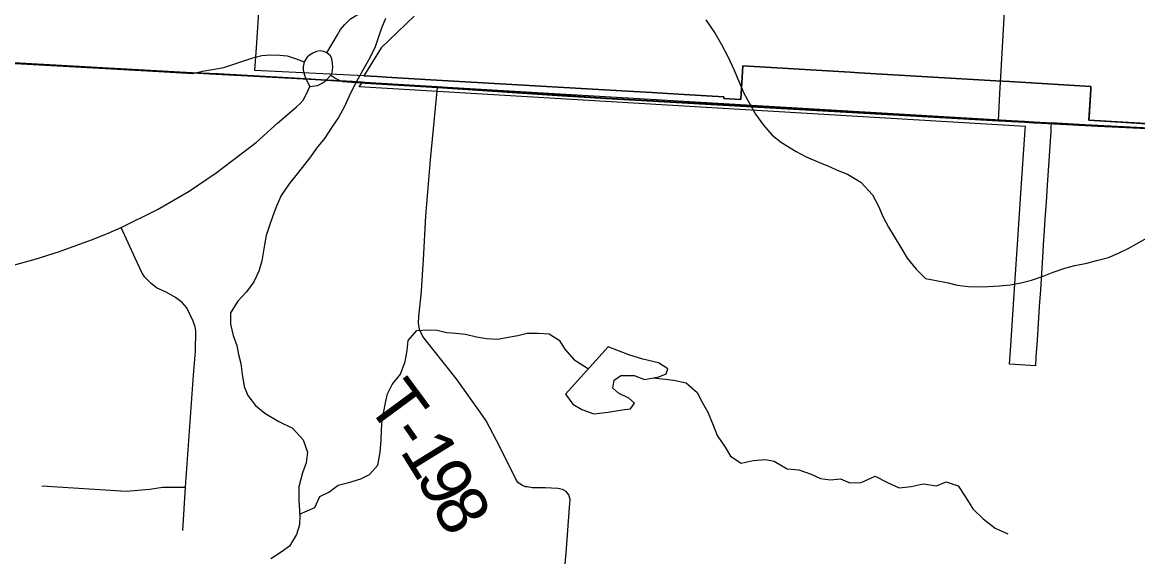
# Model space of a CAD drawing. Extents: x 208586767.6 to 208586821.4, y -134301046.9 to -134301022.9.
# Drawn here: x 208586781.515 to 208586782.765, y -134301027.656 to -134301027.057 of the extents above; entities that cross this region are included whole.
import ezdxf

# ---------------------------------------------------------------- set-up
doc = ezdxf.new("R2010")
doc.units = 0
for name, color, linetype in [('GM_X_City_Street', 7, 'Continuous'), ('GM_X_Corporation', 7, 'Continuous'), ('GM_X_County_Road', 7, 'Continuous'), ('GM_X_Minor_Lake', 7, 'Continuous'), ('GM_X_Minor_River', 7, 'Continuous'), ('GM_X_Township_Road', 7, 'Continuous'), ('GM_X_Township_Road_Text', 7, 'Continuous'), ('GM_X_US_Route', 7, 'Continuous')]:
    doc.layers.add(name, color=color, linetype=linetype)

msp = doc.modelspace()

# ---------------------------------------------------------------- linework, layer by layer
at = {"layer": 'GM_X_City_Street'}
msp.add_line((208586782.6088, -134301027.1674), (208586782.6105, -134301027.1371), dxfattribs=at)
msp.add_lwpolyline([(208586782.6105, -134301027.1371), (208586782.6116, -134301027.1179), (208586782.6197, -134301026.9727), (208586782.6245, -134301026.8881), (208586782.6251, -134301026.8711), (208586782.6247, -134301026.8638), (208586782.623, -134301026.8589), (208586782.6209, -134301026.8545), (208586782.6181, -134301026.851), (208586782.6143, -134301026.8465), (208586782.5973, -134301026.8279), (208586782.5737, -134301026.7998), (208586782.5529, -134301026.7687), (208586782.5349, -134301026.7321), (208586782.5147, -134301026.6674), (208586782.5065, -134301026.6495), (208586782.4995, -134301026.6383), (208586782.4921, -134301026.6275), (208586782.482, -134301026.6159), (208586782.4679, -134301026.6014), (208586782.4489, -134301026.5808)], dxfattribs=at)
at = {"layer": 'GM_X_Corporation'}
for points in [[(208586781.2713, -134301027.0897), (208586781.6677, -134301027.1118), (208586781.7056, -134301027.1139), (208586781.7344, -134301027.1148), (208586781.8329, -134301027.1207), (208586781.8549, -134301027.122), (208586781.8736, -134301027.1231), (208586781.98, -134301027.1295), (208586782.1685, -134301027.1422), (208586782.6086, -134301027.1669), (208586782.6378, -134301027.1684), (208586782.648, -134301027.1691), (208586782.72, -134301027.1729), (208586782.8221, -134301027.178), (208586783.5221, -134301027.2233), (208586783.9036, -134301027.2474), (208586784.2616, -134301027.2694), (208586784.8283, -134301027.3051), (208586784.8283, -134301024.0407), (208586780.8686, -134301024.0407)], [(208586782.7994, -134301027.1722), (208586782.7101, -134301027.1667), (208586782.7122, -134301027.1323), (208586782.7124, -134301027.129), (208586782.621, -134301027.1236), (208586782.6058, -134301027.1228), (208586782.4526, -134301027.1137), (208586782.4427, -134301027.1131), (208586782.3222, -134301027.106), (208586782.32, -134301027.1438), (208586782.3011, -134301027.1426), (208586782.3012, -134301027.1408), (208586782.2816, -134301027.1396), (208586782.2379, -134301027.137), (208586782.2209, -134301027.136), (208586782.1868, -134301027.134), (208586781.9791, -134301027.1219), (208586781.9227, -134301027.1186), (208586781.9125, -134301027.118), (208586781.8978, -134301027.1171), (208586781.7755, -134301027.1113), (208586781.7773, -134301027.0857), (208586781.783, -134301026.9995)], [(208586781.954, -134301027.0505), (208586781.9354, -134301027.0683), (208586781.9171, -134301027.0858), (208586781.8978, -134301027.1171), (208586781.9125, -134301027.118), (208586781.9227, -134301027.1186), (208586781.9791, -134301027.1219), (208586782.1868, -134301027.134), (208586782.2209, -134301027.136), (208586782.2379, -134301027.137), (208586782.2816, -134301027.1396), (208586782.3012, -134301027.1408), (208586782.3011, -134301027.1426), (208586782.32, -134301027.1438), (208586782.3222, -134301027.106), (208586782.4427, -134301027.1131), (208586782.4526, -134301027.1137), (208586782.6058, -134301027.1228), (208586782.621, -134301027.1236), (208586782.7124, -134301027.129), (208586782.7122, -134301027.1323), (208586782.7103, -134301027.163), (208586782.7101, -134301027.167), (208586782.7994, -134301027.1724)], [(208586780.4561, -134301030.8407), (208586784.8283, -134301030.8407), (208586784.8283, -134301027.3051), (208586784.2616, -134301027.2694), (208586783.9036, -134301027.2474), (208586783.5221, -134301027.2233), (208586782.8221, -134301027.178), (208586782.72, -134301027.1729), (208586782.648, -134301027.1691), (208586782.6378, -134301027.1684), (208586782.6086, -134301027.1669), (208586782.1685, -134301027.1422), (208586781.98, -134301027.1295), (208586781.8736, -134301027.1231), (208586781.8549, -134301027.122), (208586781.8329, -134301027.1207), (208586781.7344, -134301027.1148), (208586781.7056, -134301027.1139), (208586781.6677, -134301027.1118), (208586781.2713, -134301027.0897)], [(208586782.8175, -134301027.1789), (208586782.6679, -134301027.1698), (208586782.6675, -134301027.1757), (208586782.6673, -134301027.1796), (208586782.6633, -134301027.2396), (208586782.6621, -134301027.2585), (208586782.6608, -134301027.2774), (208586782.6596, -134301027.2963), (208586782.6593, -134301027.3006), (208586782.6576, -134301027.3266), (208586782.6557, -134301027.3567), (208586782.6544, -134301027.3755), (208586782.6532, -134301027.3944), (208586782.652, -134301027.4133), (208586782.6508, -134301027.4322), (208586782.6501, -134301027.442), (208586782.6212, -134301027.4401), (208586782.6226, -134301027.4195), (208586782.625, -134301027.3845), (208586782.6273, -134301027.35), (208586782.6306, -134301027.3006), (208586782.634, -134301027.2485), (208586782.6387, -134301027.1778), (208586782.6389, -134301027.1739), (208586781.8926, -134301027.1296), (208586781.8963, -134301027.1241), (208586781.8847, -134301027.1235), (208586781.7745, -134301027.1175), (208586781.7317, -134301027.1153), (208586781.2721, -134301027.0897)], [(208586781.2721, -134301027.0897), (208586781.7317, -134301027.1153), (208586781.7745, -134301027.1175), (208586781.8847, -134301027.1235), (208586781.8963, -134301027.1241), (208586782.6679, -134301027.1698), (208586782.8175, -134301027.1789)]]:
    msp.add_lwpolyline(points, dxfattribs=at)
at = {"layer": 'GM_X_County_Road'}
msp.add_line((208586782.6503, -134301027.1698), (208586782.6708, -134301027.1708), dxfattribs=at)
for points in [[(208586781.2615, -134301027.0897), (208586781.2715, -134301027.0903), (208586781.5878, -134301027.1079)], [(208586781.7731, -134301027.097), (208586781.7759, -134301027.0961), (208586781.7834, -134301027.0944), (208586781.793, -134301027.0936), (208586781.8034, -134301027.094), (208586781.8118, -134301027.0949), (208586781.8217, -134301027.0981), (208586781.8307, -134301027.1015)], [(208586781.5878, -134301027.1079), (208586781.6679, -134301027.1124), (208586781.7059, -134301027.1144)], [(208586781.7059, -134301027.1144), (208586781.7167, -134301027.1118), (208586781.728, -134301027.1099), (208586781.7407, -134301027.1079), (208586781.7543, -134301027.1034)], [(208586781.7543, -134301027.1034), (208586781.7563, -134301027.1027), (208586781.7731, -134301027.097)], [(208586781.8307, -134301027.1015), (208586781.8296, -134301027.1072), (208586781.8298, -134301027.1109)], [(208586781.8298, -134301027.1109), (208586781.8299, -134301027.1118), (208586781.8308, -134301027.1154), (208586781.8328, -134301027.1204)], [(208586781.8328, -134301027.1204), (208586781.8331, -134301027.1212), (208586781.8372, -134301027.1293)], [(208586781.8372, -134301027.1293), (208586781.8456, -134301027.128), (208586781.851, -134301027.1252), (208586781.8543, -134301027.1231), (208586781.8551, -134301027.1225), (208586781.8605, -134301027.1166)], [(208586781.8605, -134301027.1166), (208586781.8663, -134301027.1203), (208586781.8691, -134301027.1216)], [(208586781.8691, -134301027.1216), (208586781.8738, -134301027.1236), (208586781.8992, -134301027.1252)], [(208586781.8992, -134301027.1252), (208586781.9802, -134301027.1301), (208586782.1199, -134301027.1395)], [(208586782.1199, -134301027.1395), (208586782.1687, -134301027.1427), (208586782.6088, -134301027.1674)], [(208586782.6088, -134301027.1674), (208586782.638, -134301027.1689), (208586782.6482, -134301027.1697), (208586782.6503, -134301027.1698)], [(208586782.6708, -134301027.1708), (208586782.7202, -134301027.1734), (208586782.8141, -134301027.1782)]]:
    msp.add_lwpolyline(points, dxfattribs=at)
at = {"layer": 'GM_X_Minor_Lake'}
for points in [[(208586782.1238, -134301027.4737), (208586782.1317, -134301027.4848), (208586782.1419, -134301027.4909), (208586782.1555, -134301027.4956), (208586782.1715, -134301027.4937), (208586782.1871, -134301027.4912), (208586782.1966, -134301027.4901), (208586782.2008, -134301027.4837), (208586782.1947, -134301027.4783), (208586782.183, -134301027.4726), (208586782.1766, -134301027.4668), (208586782.1782, -134301027.4581), (208586782.1858, -134301027.4528), (208586782.2006, -134301027.4526), (208586782.2123, -134301027.4572), (208586782.2283, -134301027.4542), (208586782.2363, -134301027.4509), (208586782.2382, -134301027.4452), (208586782.228, -134301027.4387), (208586782.2102, -134301027.4344), (208586782.1947, -134301027.4297), (208586782.1716, -134301027.4205)], [(208586782.1716, -134301027.4205), (208586782.1238, -134301027.4737)]]:
    msp.add_lwpolyline(points, dxfattribs=at)
at = {"layer": 'GM_X_Minor_River'}
for points in [[(208586781.9219, -134301027.0528), (208586781.9176, -134301027.0637), (208586781.9142, -134301027.0736), (208586781.9103, -134301027.0846), (208586781.9045, -134301027.0971), (208586781.8965, -134301027.1107), (208586781.8873, -134301027.1277), (208586781.8811, -134301027.1398), (208586781.8761, -134301027.1516), (208586781.8692, -134301027.1637), (208586781.8627, -134301027.1735), (208586781.8535, -134301027.1875), (208586781.8447, -134301027.1981), (208586781.8378, -134301027.2079), (208586781.8244, -134301027.2249)], [(208586782.2809, -134301027.0545), (208586782.2914, -134301027.0698), (208586782.2986, -134301027.0819), (208586782.3057, -134301027.0957), (208586782.3124, -134301027.1101), (208586782.3173, -134301027.1223), (208586782.3233, -134301027.1364), (208586782.3293, -134301027.1474), (208586782.3364, -134301027.16), (208586782.3454, -134301027.1726), (208586782.3552, -134301027.1836), (208586782.3658, -134301027.192), (208586782.3821, -134301027.202), (208586782.3934, -134301027.2078), (208586782.4082, -134301027.2143), (208586782.4184, -134301027.2185), (208586782.4298, -134301027.2235), (208586782.4396, -134301027.2274), (208586782.4547, -134301027.2362), (208586782.4675, -134301027.2503), (208586782.4743, -134301027.2633), (208586782.4795, -134301027.2755), (208586782.4855, -134301027.2865), (208586782.4919, -134301027.2972), (208586782.5006, -134301027.3113), (208586782.5066, -134301027.3212), (208586782.5164, -134301027.3337), (208586782.5269, -134301027.3441), (208586782.5372, -134301027.346), (208586782.5523, -134301027.3491), (208586782.5626, -134301027.3515), (208586782.5751, -134301027.3531), (208586782.5861, -134301027.3535), (208586782.5971, -134301027.3532), (208586782.61, -134301027.3525), (208586782.6221, -134301027.3511), (208586782.6339, -134301027.3489), (208586782.6457, -134301027.3459), (208586782.659, -134301027.3414), (208586782.6701, -134301027.3369), (208586782.683, -134301027.3325), (208586782.6944, -134301027.3295), (208586782.7077, -134301027.3269), (208586782.7187, -134301027.3239), (208586782.732, -134301027.3206), (208586782.7431, -134301027.3157), (208586782.7541, -134301027.3105), (208586782.7636, -134301027.3052), (208586782.7754, -134301027.2985)], [(208586781.8244, -134301027.2249), (208586781.8141, -134301027.2381), (208586781.8052, -134301027.2513), (208586781.7999, -134301027.2631), (208586781.7956, -134301027.2741), (208586781.7914, -134301027.2858), (208586781.7883, -134301027.296), (208586781.7863, -134301027.3066), (208586781.7835, -134301027.3245), (208586781.78, -134301027.3358), (208586781.7743, -134301027.3479), (208586781.7662, -134301027.3589), (208586781.7563, -134301027.3695), (208586781.7482, -134301027.3827), (208586781.7482, -134301027.3952), (208586781.7511, -134301027.4078), (208586781.7552, -134301027.4192), (208586781.7574, -134301027.4291), (208586781.76, -134301027.4393), (208586781.7615, -134301027.4511), (208586781.7637, -134301027.4651), (208586781.7678, -134301027.475), (208586781.7764, -134301027.4865), (208586781.7866, -134301027.4949), (208586781.8025, -134301027.5041), (208586781.8176, -134301027.5118), (208586781.8297, -134301027.5247), (208586781.8346, -134301027.5388), (208586781.833, -134301027.5506), (208586781.8291, -134301027.5619), (208586781.8248, -134301027.5775), (208586781.8247, -134301027.5927), (208586781.8258, -134301027.6097), (208586781.8257, -134301027.62), (208586781.8222, -134301027.631), (208586781.8145, -134301027.6438), (208586781.805, -134301027.6506), (208586781.7936, -134301027.6581)], [(208586781.8256, -134301027.6079), (208586781.8429, -134301027.6007), (208586781.8483, -134301027.5882), (208586781.8586, -134301027.5834), (208586781.8689, -134301027.5755), (208586781.881, -134301027.5725), (208586781.8943, -134301027.5684), (208586781.9039, -134301027.5635), (208586781.9134, -134301027.5533), (208586781.9158, -134301027.5385), (208586781.917, -134301027.5256), (208586781.9175, -134301027.5131), (208586781.9183, -134301027.5033), (208586781.9199, -134301027.493), (208586781.9218, -134301027.4832), (208586781.9242, -134301027.4733), (208586781.9295, -134301027.4627), (208586781.9387, -134301027.4514), (208586781.9441, -134301027.437), (208586781.9461, -134301027.4249), (208586781.9473, -134301027.4135), (208586781.9569, -134301027.4022), (208586781.9694, -134301027.4018), (208586781.98, -134301027.4019), (208586781.9902, -134301027.4046), (208586782.0009, -134301027.4054), (208586782.0115, -134301027.4066), (208586782.024, -134301027.4094), (208586782.035, -134301027.4113), (208586782.0479, -134301027.4122), (208586782.0593, -134301027.41), (208586782.0703, -134301027.4078), (208586782.0806, -134301027.4055), (208586782.0931, -134301027.4052), (208586782.1052, -134301027.4061), (208586782.1166, -134301027.4133), (208586782.123, -134301027.4232), (208586782.1331, -134301027.4347), (208586782.1493, -134301027.4453)], [(208586782.2223, -134301027.4553), (208586782.245, -134301027.4581), (208586782.259, -134301027.4609), (208586782.2711, -134301027.4719), (208586782.2771, -134301027.4834), (208586782.2831, -134301027.494), (208586782.2891, -134301027.5085), (208586782.2935, -134301027.5199), (208586782.3026, -134301027.5332), (208586782.3086, -134301027.5431), (208586782.3203, -134301027.5508), (208586782.334, -134301027.5478), (208586782.3476, -134301027.5468), (208586782.3575, -134301027.5487), (208586782.3719, -134301027.5572), (208586782.3851, -134301027.5584), (208586782.3988, -134301027.5634), (208586782.4094, -134301027.568), (208586782.4207, -134301027.5696), (208586782.4318, -134301027.5685), (208586782.4424, -134301027.5728), (208586782.4549, -134301027.5725), (208586782.4705, -134301027.5654), (208586782.4845, -134301027.5727), (208586782.4974, -134301027.5784), (208586782.511, -134301027.577), (208586782.5243, -134301027.574), (208586782.5395, -134301027.5764), (208586782.5502, -134301027.5719), (208586782.5638, -134301027.5765), (208586782.5721, -134301027.5895), (208586782.5799, -134301027.6021), (208586782.5916, -134301027.6131), (208586782.6049, -134301027.6238), (208586782.6192, -134301027.63)]]:
    msp.add_lwpolyline(points, dxfattribs=at)
at = {"layer": 'GM_X_Township_Road'}
for points in [[(208586781.9643, -134301027.3284), (208586781.9647, -134301027.3233), (208586781.9671, -134301027.2738), (208586781.9725, -134301027.2112), (208586781.9802, -134301027.1301)], [(208586781.6948, -134301027.6263), (208586781.6977, -134301027.578), (208586781.7068, -134301027.4523), (208586781.7089, -134301027.4255), (208586781.7093, -134301027.4028), (208586781.7087, -134301027.3982), (208586781.7064, -134301027.3918), (208586781.6992, -134301027.377), (208586781.6941, -134301027.371), (208586781.6866, -134301027.3653), (208586781.6769, -134301027.3597), (208586781.6653, -134301027.3544), (208586781.6594, -134301027.3499), (208586781.6521, -134301027.3425), (208586781.6491, -134301027.338), (208586781.6413, -134301027.3212), (208586781.6256, -134301027.287)], [(208586781.9621, -134301027.3587), (208586781.9622, -134301027.3578), (208586781.9643, -134301027.3284)], [(208586781.975, -134301027.4231), (208586781.9638, -134301027.409), (208586781.9599, -134301027.4014), (208586781.959, -134301027.3941), (208586781.9592, -134301027.3868), (208586781.9621, -134301027.3587)], [(208586782.0807, -134301027.5776), (208586782.0787, -134301027.5773), (208586782.0748, -134301027.5755), (208586782.0711, -134301027.573), (208586782.0688, -134301027.5702), (208586782.0501, -134301027.5328), (208586782.0347, -134301027.5037), (208586782.0281, -134301027.4939), (208586782.0011, -134301027.4561), (208586781.975, -134301027.4231)], [(208586781.537, -134301027.5765), (208586781.6314, -134301027.5823), (208586781.6579, -134301027.58), (208586781.672, -134301027.578), (208586781.6977, -134301027.578)], [(208586782.1124, -134301027.8249), (208586782.1194, -134301027.7029), (208586782.1245, -134301027.6519), (208586782.1281, -134301027.6007), (208586782.1288, -134301027.5917), (208586782.1274, -134301027.5863), (208586782.1245, -134301027.5826), (208586782.1201, -134301027.5803), (208586782.1149, -134301027.5792), (208586782.1009, -134301027.5787), (208586782.0865, -134301027.5785), (208586782.0807, -134301027.5776)]]:
    msp.add_lwpolyline(points, dxfattribs=at)
at = {"layer": 'GM_X_US_Route'}
msp.add_line((208586781.611, -134301027.2932), (208586781.6256, -134301027.287), dxfattribs=at)
for points in [[(208586781.8561, -134301027.0915), (208586781.868, -134301027.0712), (208586781.8716, -134301027.0653), (208586781.8763, -134301027.0595), (208586781.8826, -134301027.0535), (208586781.8882, -134301027.0498), (208586781.8981, -134301027.0454), (208586781.9231, -134301027.0346), (208586781.949, -134301027.0225)], [(208586781.8561, -134301027.0915), (208586781.8528, -134301027.0898), (208586781.8486, -134301027.0891), (208586781.8447, -134301027.0898), (208586781.8405, -134301027.0918), (208586781.8368, -134301027.0939), (208586781.8341, -134301027.0963), (208586781.8307, -134301027.1015)], [(208586781.8605, -134301027.1166), (208586781.862, -134301027.1136), (208586781.8629, -134301027.1076), (208586781.8626, -134301027.1029), (208586781.8618, -134301027.0982), (208586781.8603, -134301027.0949), (208586781.8561, -134301027.0915)], [(208586781.8307, -134301027.1015), (208586781.8296, -134301027.1072), (208586781.8298, -134301027.1109)], [(208586781.8298, -134301027.1109), (208586781.8299, -134301027.1118), (208586781.8308, -134301027.1154), (208586781.8328, -134301027.1204)], [(208586781.8328, -134301027.1204), (208586781.8331, -134301027.1212), (208586781.8372, -134301027.1293)], [(208586781.8372, -134301027.1293), (208586781.8456, -134301027.128), (208586781.851, -134301027.1252), (208586781.8543, -134301027.1231), (208586781.8551, -134301027.1225), (208586781.8605, -134301027.1166)], [(208586781.7603, -134301027.2046), (208586781.7775, -134301027.1916), (208586781.8008, -134301027.1701), (208586781.8221, -134301027.1518), (208586781.8263, -134301027.148), (208586781.8295, -134301027.1445), (208586781.8335, -134301027.1375), (208586781.8372, -134301027.1293)], [(208586781.6256, -134301027.287), (208586781.6665, -134301027.2668), (208586781.7018, -134301027.2462), (208586781.7322, -134301027.2257), (208586781.7603, -134301027.2046)], [(208586781.2851, -134301027.438), (208586781.3021, -134301027.4262), (208586781.3686, -134301027.3802), (208586781.3831, -134301027.3711), (208586781.4002, -134301027.362), (208586781.4168, -134301027.355), (208586781.4232, -134301027.3532), (208586781.4466, -134301027.3461), (208586781.5051, -134301027.3291), (208586781.5295, -134301027.3226), (208586781.5566, -134301027.314), (208586781.5955, -134301027.2998), (208586781.6074, -134301027.2948), (208586781.611, -134301027.2932)]]:
    msp.add_lwpolyline(points, dxfattribs=at)

# ---------------------------------------------------------------- texts
at = {"layer": 'GM_X_Township_Road_Text'}
for s, rotation, p in [('T', 306.4225, (208586781.8996, -134301027.4848)), ('-', 304.8571, (208586781.9246, -134301027.5187)), ('1', 301.6921, (208586781.9374, -134301027.5371)), ('9', 297.5123, (208586781.9553, -134301027.566)), ('8', 299.9794, (208586781.9727, -134301027.5994))]:
    msp.add_text(s, height=0.0568, rotation=rotation, dxfattribs=at).set_placement(p)

doc.saveas('drawing.dxf')
